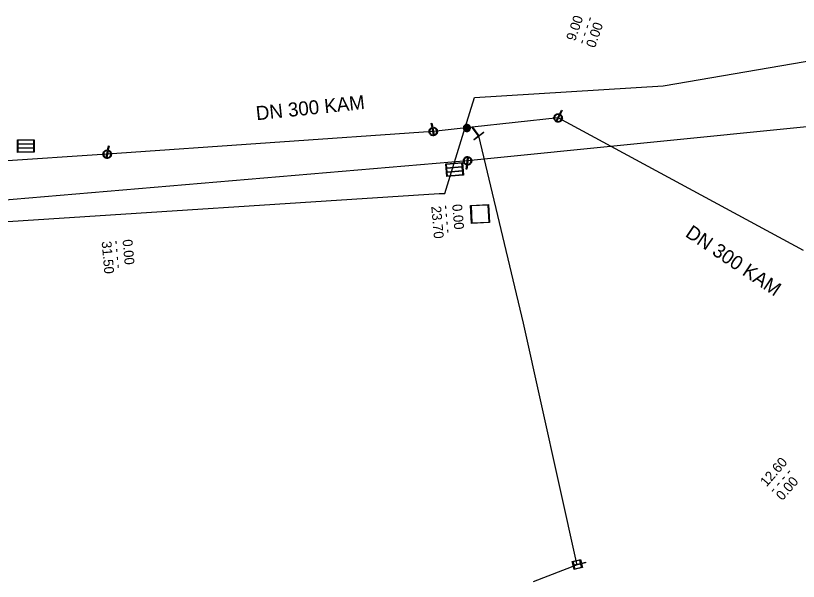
# Model space of a CAD drawing. Extents: x -818321 to -817653, y -1049725 to -1049329.
# Drawn here: x -817974.2 to -817918.3, y -1049437.1 to -1049396.7 of the extents above; entities that cross this region are included whole.
import ezdxf

# ---------------------------------------------------------------- set-up
doc = ezdxf.new("R2010")
doc.units = 0
doc.layers.add('Default', color=7, linetype='Continuous')
doc.layers.add('Level 0', color=7, linetype='Continuous')

msp = doc.modelspace()

# ---------------------------------------------------------------- linework, layer by layer
at = {"layer": 'Default'}
for points in [[(-817935.323, -1049403.725), (-817935.191, -1049403.455), (-817935.147, -1049403.476), (-817935.279, -1049403.746)], [(-817935.564, -1049404.218), (-817935.345, -1049403.771)], [(-817935.301, -1049403.792), (-817935.519, -1049404.239)], [(-817944.435, -1049404.687), (-817944.498, -1049404.393), (-817944.45, -1049404.383), (-817944.387, -1049404.677)], [(-817944.321, -1049405.224), (-817944.425, -1049404.737)], [(-817944.376, -1049404.727), (-817944.273, -1049405.214)], [(-817941.569, -1049404.669), (-817941.548, -1049404.666), (-817941.087, -1049405.278), (-817940.749, -1049405.023), (-817940.731, -1049405.047), (-817941.432, -1049405.576), (-817941.45, -1049405.552), (-817941.111, -1049405.296), (-817941.566, -1049404.694), (-817941.569, -1049404.669)], [(-817972.843, -1049406.463), (-817974.043, -1049406.464), (-817974.043, -1049405.563), (-817972.843, -1049405.563), (-817972.843, -1049406.463)], [(-817972.88, -1049405.851), (-817972.88, -1049405.6), (-817974.005, -1049405.6), (-817974.005, -1049405.851), (-817972.88, -1049405.851)], [(-817972.88, -1049406.136), (-817972.88, -1049405.888), (-817974.005, -1049405.888), (-817974.005, -1049406.136), (-817972.88, -1049406.136)], [(-817972.88, -1049406.173), (-817974.005, -1049406.173), (-817974.005, -1049406.426), (-817972.88, -1049406.426), (-817972.88, -1049406.173)], [(-817967.703, -1049406.835), (-817967.608, -1049406.347)], [(-817967.559, -1049406.356), (-817967.654, -1049406.844)], [(-817967.598, -1049406.297), (-817967.541, -1049406.001), (-817967.492, -1049406.011), (-817967.55, -1049406.306)], [(-817941.952, -1049407.316), (-817941.9, -1049406.822)], [(-817941.851, -1049406.827), (-817941.903, -1049407.321)], [(-817942.186, -1049408.088), (-817943.381, -1049408.194), (-817943.459, -1049407.296), (-817942.264, -1049407.191), (-817942.186, -1049408.088)], [(-817942.276, -1049407.482), (-817942.298, -1049407.232), (-817943.419, -1049407.33), (-817943.397, -1049407.58), (-817942.276, -1049407.482)], [(-817942.251, -1049407.765), (-817942.273, -1049407.519), (-817943.394, -1049407.617), (-817943.372, -1049407.864), (-817942.251, -1049407.765)], [(-817941.908, -1049407.372), (-817941.94, -1049407.671), (-817941.989, -1049407.666), (-817941.957, -1049407.367)], [(-817942.248, -1049407.803), (-817943.369, -1049407.901), (-817943.347, -1049408.153), (-817942.226, -1049408.055), (-817942.248, -1049407.803)], [(-817941.691, -1049410.257), (-817940.393, -1049410.189), (-817940.325, -1049411.487), (-817941.623, -1049411.555), (-817941.691, -1049410.257)], [(-817941.585, -1049411.513), (-817940.368, -1049411.449), (-817940.431, -1049410.232), (-817941.649, -1049410.296), (-817941.585, -1049411.513)], [(-817933.775, -1049435.828), (-817933.483, -1049435.76), (-817933.472, -1049435.808), (-817933.764, -1049435.876), (-817933.702, -1049436.144), (-817934.287, -1049436.279), (-817934.422, -1049435.694), (-817933.837, -1049435.559), (-817933.775, -1049435.828)], [(-817933.823, -1049435.839), (-817933.874, -1049435.618), (-817934.363, -1049435.731), (-817934.312, -1049435.952), (-817933.823, -1049435.839)], [(-817933.812, -1049435.887), (-817934.301, -1049436), (-817934.25, -1049436.22), (-817933.761, -1049436.107), (-817933.812, -1049435.887)]]:
    msp.add_lwpolyline(points, dxfattribs=at)
for points in [[(-817935.279, -1049403.746), (-817935.225, -1049403.777), (-817935.184, -1049403.836), (-817935.137, -1049403.903), (-817935.133, -1049403.985), (-817935.128, -1049404.066), (-817935.163, -1049404.136), (-817935.197, -1049404.207), (-817935.265, -1049404.254), (-817935.333, -1049404.301), (-817935.414, -1049404.304), (-817935.495, -1049404.308), (-817935.564, -1049404.274), (-817935.632, -1049404.241), (-817935.679, -1049404.175), (-817935.727, -1049404.109), (-817935.732, -1049404.026), (-817935.736, -1049403.944), (-817935.702, -1049403.873), (-817935.668, -1049403.803), (-817935.601, -1049403.756), (-817935.534, -1049403.709), (-817935.453, -1049403.705), (-817935.381, -1049403.701), (-817935.323, -1049403.725)], [(-817935.345, -1049403.771), (-817935.391, -1049403.752), (-817935.45, -1049403.755), (-817935.518, -1049403.759), (-817935.573, -1049403.798), (-817935.629, -1049403.837), (-817935.657, -1049403.895), (-817935.686, -1049403.953), (-817935.682, -1049404.022), (-817935.678, -1049404.091), (-817935.638, -1049404.146), (-817935.604, -1049404.193), (-817935.564, -1049404.218)], [(-817935.519, -1049404.239), (-817935.475, -1049404.256), (-817935.416, -1049404.254), (-817935.349, -1049404.252), (-817935.292, -1049404.212), (-817935.236, -1049404.173), (-817935.207, -1049404.114), (-817935.179, -1049404.056), (-817935.182, -1049403.988), (-817935.186, -1049403.921), (-817935.225, -1049403.865), (-817935.259, -1049403.817), (-817935.301, -1049403.792)], [(-817944.387, -1049404.677), (-817944.325, -1049404.668), (-817944.257, -1049404.69), (-817944.179, -1049404.713), (-817944.125, -1049404.775), (-817944.072, -1049404.837), (-817944.055, -1049404.913), (-817944.039, -1049404.99), (-817944.064, -1049405.068), (-817944.088, -1049405.147), (-817944.15, -1049405.2), (-817944.212, -1049405.253), (-817944.287, -1049405.269), (-817944.36, -1049405.284), (-817944.439, -1049405.261), (-817944.517, -1049405.238), (-817944.572, -1049405.176), (-817944.626, -1049405.114), (-817944.642, -1049405.037), (-817944.659, -1049404.961), (-817944.635, -1049404.883), (-817944.611, -1049404.805), (-817944.549, -1049404.752), (-817944.495, -1049404.704), (-817944.435, -1049404.687)], [(-817944.425, -1049404.737), (-817944.472, -1049404.751), (-817944.517, -1049404.79), (-817944.568, -1049404.834), (-817944.587, -1049404.899), (-817944.607, -1049404.964), (-817944.594, -1049405.027), (-817944.58, -1049405.091), (-817944.535, -1049405.142), (-817944.489, -1049405.194), (-817944.424, -1049405.213), (-817944.368, -1049405.23), (-817944.321, -1049405.224)], [(-817944.273, -1049405.214), (-817944.227, -1049405.2), (-817944.183, -1049405.162), (-817944.131, -1049405.118), (-817944.111, -1049405.052), (-817944.091, -1049404.987), (-817944.104, -1049404.923), (-817944.118, -1049404.859), (-817944.162, -1049404.808), (-817944.207, -1049404.757), (-817944.272, -1049404.738), (-817944.328, -1049404.72), (-817944.376, -1049404.727)], [(-817941.946, -1049404.472), (-817941.883, -1049404.472), (-817941.824, -1049404.504), (-817941.764, -1049404.536), (-817941.73, -1049404.596), (-817941.696, -1049404.657), (-817941.696, -1049404.722), (-817941.696, -1049404.787), (-817941.729, -1049404.846), (-817941.762, -1049404.906), (-817941.822, -1049404.939), (-817941.881, -1049404.972), (-817941.946, -1049404.972), (-817942.011, -1049404.972), (-817942.071, -1049404.939), (-817942.13, -1049404.906), (-817942.163, -1049404.846), (-817942.196, -1049404.787), (-817942.196, -1049404.722), (-817942.196, -1049404.657), (-817942.163, -1049404.596), (-817942.129, -1049404.536), (-817942.069, -1049404.504), (-817942.01, -1049404.472), (-817941.946, -1049404.472)], [(-817941.946, -1049404.495), (-817942.004, -1049404.495), (-817942.058, -1049404.524), (-817942.112, -1049404.554), (-817942.142, -1049404.608), (-817942.173, -1049404.663), (-817942.173, -1049404.722), (-817942.173, -1049404.781), (-817942.143, -1049404.835), (-817942.113, -1049404.889), (-817942.059, -1049404.918), (-817942.005, -1049404.948), (-817941.946, -1049404.948), (-817941.887, -1049404.948), (-817941.833, -1049404.918), (-817941.779, -1049404.889), (-817941.749, -1049404.835), (-817941.72, -1049404.781), (-817941.72, -1049404.722), (-817941.72, -1049404.663), (-817941.75, -1049404.608), (-817941.781, -1049404.554), (-817941.835, -1049404.524), (-817941.889, -1049404.495), (-817941.946, -1049404.495)], [(-817941.946, -1049404.512), (-817941.893, -1049404.512), (-817941.844, -1049404.539), (-817941.794, -1049404.566), (-817941.765, -1049404.617), (-817941.737, -1049404.667), (-817941.737, -1049404.722), (-817941.737, -1049404.777), (-817941.764, -1049404.826), (-817941.792, -1049404.876), (-817941.842, -1049404.904), (-817941.892, -1049404.931), (-817941.946, -1049404.931), (-817942.001, -1049404.931), (-817942.051, -1049404.904), (-817942.101, -1049404.876), (-817942.128, -1049404.826), (-817942.156, -1049404.777), (-817942.156, -1049404.722), (-817942.156, -1049404.667), (-817942.128, -1049404.617), (-817942.1, -1049404.566), (-817942.049, -1049404.539), (-817941.999, -1049404.512), (-817941.946, -1049404.512)], [(-817941.947, -1049404.534), (-817942.025, -1049404.534), (-817942.079, -1049404.589), (-817942.134, -1049404.644), (-817942.134, -1049404.722), (-817942.134, -1049404.8), (-817942.079, -1049404.855), (-817942.024, -1049404.909), (-817941.947, -1049404.909), (-817941.869, -1049404.909), (-817941.814, -1049404.855), (-817941.759, -1049404.8), (-817941.759, -1049404.722), (-817941.759, -1049404.644), (-817941.813, -1049404.589), (-817941.868, -1049404.534), (-817941.947, -1049404.534)], [(-817941.947, -1049404.557), (-817941.878, -1049404.557), (-817941.83, -1049404.605), (-817941.783, -1049404.653), (-817941.783, -1049404.721), (-817941.783, -1049404.789), (-817941.831, -1049404.837), (-817941.879, -1049404.885), (-817941.947, -1049404.885), (-817942.015, -1049404.885), (-817942.063, -1049404.837), (-817942.111, -1049404.789), (-817942.111, -1049404.721), (-817942.111, -1049404.653), (-817942.063, -1049404.605), (-817942.015, -1049404.557), (-817941.947, -1049404.557)], [(-817941.947, -1049404.577), (-817942.007, -1049404.577), (-817942.049, -1049404.619), (-817942.091, -1049404.662), (-817942.091, -1049404.721), (-817942.091, -1049404.781), (-817942.049, -1049404.823), (-817942.007, -1049404.866), (-817941.947, -1049404.866), (-817941.887, -1049404.866), (-817941.845, -1049404.823), (-817941.802, -1049404.781), (-817941.802, -1049404.721), (-817941.802, -1049404.662), (-817941.844, -1049404.619), (-817941.886, -1049404.577), (-817941.947, -1049404.577)], [(-817941.946, -1049404.597), (-817941.894, -1049404.597), (-817941.858, -1049404.633), (-817941.821, -1049404.67), (-817941.821, -1049404.722), (-817941.821, -1049404.774), (-817941.858, -1049404.81), (-817941.894, -1049404.847), (-817941.946, -1049404.847), (-817941.998, -1049404.847), (-817942.035, -1049404.81), (-817942.071, -1049404.774), (-817942.071, -1049404.722), (-817942.071, -1049404.67), (-817942.035, -1049404.633), (-817941.999, -1049404.597), (-817941.946, -1049404.597)], [(-817941.946, -1049404.62), (-817941.989, -1049404.62), (-817942.018, -1049404.65), (-817942.048, -1049404.679), (-817942.048, -1049404.722), (-817942.048, -1049404.764), (-817942.018, -1049404.793), (-817941.989, -1049404.823), (-817941.946, -1049404.823), (-817941.904, -1049404.823), (-817941.875, -1049404.793), (-817941.845, -1049404.764), (-817941.845, -1049404.722), (-817941.845, -1049404.679), (-817941.875, -1049404.65), (-817941.904, -1049404.62), (-817941.946, -1049404.62)], [(-817941.946, -1049404.637), (-817941.911, -1049404.637), (-817941.887, -1049404.662), (-817941.862, -1049404.686), (-817941.862, -1049404.722), (-817941.862, -1049404.757), (-817941.887, -1049404.781), (-817941.912, -1049404.806), (-817941.946, -1049404.806), (-817941.982, -1049404.806), (-817942.006, -1049404.781), (-817942.031, -1049404.757), (-817942.031, -1049404.722), (-817942.031, -1049404.686), (-817942.006, -1049404.662), (-817941.982, -1049404.637), (-817941.946, -1049404.637)], [(-817941.946, -1049404.659), (-817941.972, -1049404.659), (-817941.991, -1049404.678), (-817942.009, -1049404.696), (-817942.009, -1049404.722), (-817942.009, -1049404.748), (-817941.99, -1049404.766), (-817941.972, -1049404.784), (-817941.946, -1049404.784), (-817941.92, -1049404.784), (-817941.902, -1049404.766), (-817941.884, -1049404.748), (-817941.884, -1049404.722), (-817941.884, -1049404.696), (-817941.902, -1049404.678), (-817941.92, -1049404.659), (-817941.946, -1049404.659)], [(-817941.946, -1049404.683), (-817941.93, -1049404.683), (-817941.919, -1049404.694), (-817941.907, -1049404.705), (-817941.907, -1049404.722), (-817941.907, -1049404.738), (-817941.919, -1049404.749), (-817941.93, -1049404.761), (-817941.946, -1049404.761), (-817941.963, -1049404.761), (-817941.974, -1049404.749), (-817941.986, -1049404.738), (-817941.986, -1049404.722), (-817941.986, -1049404.705), (-817941.974, -1049404.694), (-817941.963, -1049404.683), (-817941.946, -1049404.683)], [(-817941.946, -1049404.698), (-817941.956, -1049404.698), (-817941.963, -1049404.705), (-817941.97, -1049404.712), (-817941.97, -1049404.722), (-817941.97, -1049404.732), (-817941.963, -1049404.738), (-817941.956, -1049404.745), (-817941.946, -1049404.745), (-817941.936, -1049404.745), (-817941.93, -1049404.738), (-817941.923, -1049404.732), (-817941.923, -1049404.722), (-817941.923, -1049404.712), (-817941.93, -1049404.705), (-817941.936, -1049404.698), (-817941.946, -1049404.698)], [(-817967.55, -1049406.306), (-817967.49, -1049406.322), (-817967.435, -1049406.368), (-817967.372, -1049406.42), (-817967.347, -1049406.498), (-817967.322, -1049406.576), (-817967.337, -1049406.652), (-817967.351, -1049406.729), (-817967.405, -1049406.792), (-817967.458, -1049406.856), (-817967.536, -1049406.88), (-817967.613, -1049406.904), (-817967.688, -1049406.89), (-817967.762, -1049406.875), (-817967.826, -1049406.824), (-817967.889, -1049406.772), (-817967.915, -1049406.693), (-817967.94, -1049406.615), (-817967.925, -1049406.538), (-817967.911, -1049406.461), (-817967.858, -1049406.399), (-817967.806, -1049406.336), (-817967.728, -1049406.311), (-817967.66, -1049406.289), (-817967.598, -1049406.297)], [(-817967.608, -1049406.347), (-817967.657, -1049406.341), (-817967.713, -1049406.359), (-817967.777, -1049406.38), (-817967.821, -1049406.432), (-817967.864, -1049406.484), (-817967.877, -1049406.547), (-817967.889, -1049406.611), (-817967.867, -1049406.677), (-817967.846, -1049406.742), (-817967.793, -1049406.785), (-817967.748, -1049406.822), (-817967.703, -1049406.835)], [(-817967.654, -1049406.844), (-817967.607, -1049406.849), (-817967.551, -1049406.832), (-817967.486, -1049406.812), (-817967.442, -1049406.759), (-817967.398, -1049406.707), (-817967.385, -1049406.643), (-817967.373, -1049406.579), (-817967.394, -1049406.515), (-817967.415, -1049406.45), (-817967.467, -1049406.407), (-817967.512, -1049406.369), (-817967.559, -1049406.356)], [(-817941.957, -1049407.367), (-817942.019, -1049407.356), (-817942.077, -1049407.315), (-817942.144, -1049407.268), (-817942.176, -1049407.193), (-817942.208, -1049407.118), (-817942.2, -1049407.04), (-817942.192, -1049406.962), (-817942.144, -1049406.895), (-817942.096, -1049406.827), (-817942.021, -1049406.796), (-817941.946, -1049406.765), (-817941.87, -1049406.773), (-817941.795, -1049406.781), (-817941.728, -1049406.827), (-817941.66, -1049406.873), (-817941.628, -1049406.949), (-817941.595, -1049407.025), (-817941.603, -1049407.103), (-817941.611, -1049407.181), (-817941.658, -1049407.248), (-817941.705, -1049407.315), (-817941.78, -1049407.346), (-817941.846, -1049407.375), (-817941.908, -1049407.372)], [(-817941.9, -1049406.822), (-817941.948, -1049406.821), (-817942.002, -1049406.843), (-817942.064, -1049406.868), (-817942.104, -1049406.925), (-817942.143, -1049406.981), (-817942.15, -1049407.046), (-817942.157, -1049407.11), (-817942.131, -1049407.173), (-817942.104, -1049407.235), (-817942.048, -1049407.274), (-817942, -1049407.308), (-817941.952, -1049407.316)], [(-817941.903, -1049407.321), (-817941.854, -1049407.323), (-817941.799, -1049407.3), (-817941.737, -1049407.273), (-817941.698, -1049407.218), (-817941.659, -1049407.163), (-817941.653, -1049407.098), (-817941.646, -1049407.033), (-817941.673, -1049406.97), (-817941.7, -1049406.907), (-817941.756, -1049406.868), (-817941.804, -1049406.836), (-817941.851, -1049406.827)]]:
    msp.add_open_spline(points, degree=3, dxfattribs=at)
at = {"layer": 'Level 0'}
for p, q in [((-817927.943, -1049401.705), (-817901.349, -1049397.13)), ((-817941.392, -1049402.533), (-817927.943, -1049401.705)), ((-817942.059, -1049404.681), (-817941.392, -1049402.533)), ((-817911.864, -1049404.061), (-817941.902, -1049407.077)), ((-817935.43, -1049404), (-817941.567, -1049404.665)), ((-817917.917, -1049413.467), (-817935.43, -1049404)), ((-817941.567, -1049404.665), (-817944.35, -1049404.97)), ((-817943.526, -1049409.409), (-817942.059, -1049404.681)), ((-817941.085, -1049405.292), (-817941.567, -1049404.665)), ((-817944.35, -1049404.97), (-817967.63, -1049406.59)), ((-817937.911, -1049418.672), (-817941.085, -1049405.292)), ((-817967.63, -1049406.59), (-817999.23, -1049408.74)), ((-817941.902, -1049407.077), (-817991.33, -1049411.28)), ((-818009.819, -1049413.691), (-817943.938, -1049409.416)), ((-817943.938, -1049409.416), (-817943.526, -1049409.409)), ((-817934.069, -1049435.97), (-817937.911, -1049418.672)), ((-817937.19, -1049437.123), (-817934.053, -1049435.915))]:
    msp.add_line(p, q, dxfattribs=at)

# ---------------------------------------------------------------- texts
for s, height, rotation, p in [('9.00', 0.7, 71, (-817934.22, -1049398.555)), ('- - - -', 0.7, 71, (-817933.511, -1049398.799)), ('0.00', 0.7, 71, (-817932.802, -1049399.043)), ('DN 300 KAM', 1, 6, (-817956.959, -1049404.175)), ('23.70', 0.7, 275, (-817944.493, -1049410.326)), ('- - - -', 0.7, 275, (-817943.746, -1049410.259)), ('0.00', 0.7, 275, (-817942.999, -1049410.193)), ('DN 300 KAM', 1, 326, (-817926.419, -1049412.427)), ('31.50', 0.7, 275, (-817968.029, -1049412.841)), ('- - - -', 0.7, 275, (-817967.281, -1049412.776)), ('0.00', 0.7, 275, (-817966.534, -1049412.711)), ('12.60', 0.7, 49, (-817920.551, -1049430.41)), ('- - - -', 0.7, 49, (-817919.985, -1049430.901)), ('0.00', 0.7, 49, (-817919.419, -1049431.393))]:
    msp.add_text(s, height=height, rotation=rotation, dxfattribs=at).set_placement(p)

doc.saveas('drawing.dxf')
